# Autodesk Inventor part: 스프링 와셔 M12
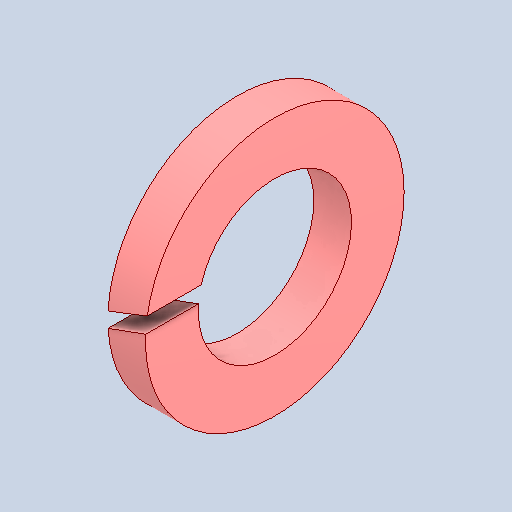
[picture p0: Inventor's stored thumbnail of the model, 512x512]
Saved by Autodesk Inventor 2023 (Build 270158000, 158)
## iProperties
Created: 2025-03
Part Number: 스프링 와셔 M12
Material: 강철, 연강
Description: 스프링 잠금 와셔
Document SubType Name: Modeling
Designer: Admin
Density: 7.85 g/cm^3
Appearance: 기본값
Author: jhkim
Sending System: Autodesk Inventor 2025
Preprocessor: ST-DEVELOPER v20
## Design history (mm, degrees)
feature "Solid1"
node "솔리드1"
